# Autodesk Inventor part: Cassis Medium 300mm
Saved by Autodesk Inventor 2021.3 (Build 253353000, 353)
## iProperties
Created: 2023-09
Part Number: Cassis Medium 300mm
Material: Generic
Document SubType Name: Modeling
Designer: AdminForWorker
Density: 1 g/cm^3
Appearance: Default
Title: Cassis Medium 300mm v4
Author: AdminForWorker
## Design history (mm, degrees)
feature "Body1"
feature "Body2"
feature "Body7"
feature "Body3"
feature "Body4"
feature "Body5"
feature "Body6"
body "Solid1"
body "Solid2"
body "Solid3"
body "Solid4"
body "Solid5"
body "Solid6"
body "Solid7"
